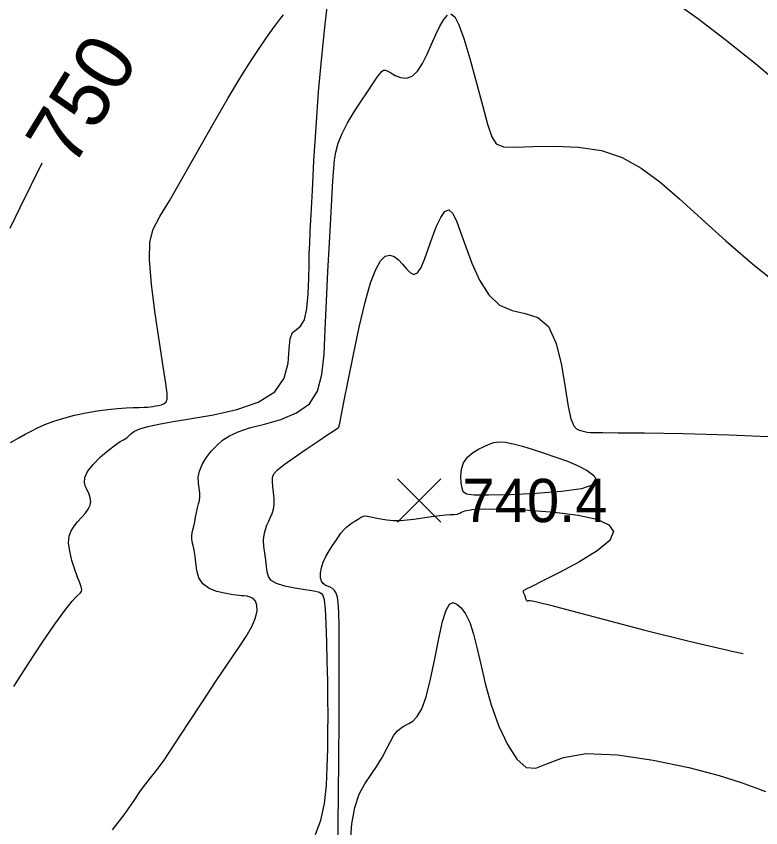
# Model space of a CAD drawing. Extents: x 2566142 to 2571431, y 418755 to 421584.
# Drawn here: x 2567510.6 to 2567768.3, y 420429 to 420710 of the extents above; entities that cross this region are included whole.
import ezdxf

# ---------------------------------------------------------------- set-up
doc = ezdxf.new("R2010")
doc.units = 0
for name, color, linetype in [('Contour_ADS_Label_Major', 7, 'Continuous'), ('Contour_ADS_Major', 7, 'Continuous'), ('Contour_ADS_Minor', 7, 'Continuous'), ('Contour_ADS_Spot_Elevation', 7, 'Continuous')]:
    doc.layers.add(name, color=color, linetype=linetype)

# ---------------------------------------------------------------- blocks, each defined once
blk = doc.blocks.new('S750')
at = {"layer": 'Contour_ADS_Spot_Elevation'}
for p, q in [((-0.5, 0.498), (0.5, -0.498)), ((-0.498, -0.5), (0.498, 0.5))]:
    blk.add_line(p, q, dxfattribs=at)

msp = doc.modelspace()

# ---------------------------------------------------------------- linework, layer by layer
at = {"layer": 'Contour_ADS_Major'}
for points in [[(2567508.51, 420636.59), (2567511.88, 420643.75), (2567515.73, 420651.47), (2567519.59, 420659.15)], [(2567621.88, 420422.89), (2567622.06, 420430.49), (2567622.18, 420440.5), (2567622.27, 420452.9), (2567622.33, 420466.44), (2567622.37, 420479.56), (2567622.38, 420490.67), (2567622.35, 420498.61), (2567622.25, 420503.76), (2567622.06, 420506.91), (2567621.75, 420508.83), (2567621.3, 420510.17), (2567620.71, 420511.15), (2567620.01, 420511.82), (2567619.21, 420512.29), (2567618.35, 420512.63), (2567617.51, 420512.98), (2567616.77, 420513.5), (2567616.21, 420514.32), (2567615.92, 420515.56), (2567615.91, 420517.15), (2567616.21, 420518.98), (2567616.83, 420520.93), (2567617.75, 420522.92), (2567618.87, 420524.86), (2567620.06, 420526.68), (2567621.17, 420528.32), (2567622.12, 420529.73), (2567622.99, 420530.95), (2567623.88, 420532.04), (2567624.92, 420533.08), (2567626.19, 420534.1), (2567627.56, 420535.06), (2567628.88, 420535.88), (2567629.99, 420536.49), (2567630.8, 420536.83), (2567631.46, 420536.94), (2567632.21, 420536.85), (2567633.27, 420536.61), (2567634.8, 420536.27), (2567636.73, 420535.9), (2567638.91, 420535.59), (2567641.22, 420535.4), (2567643.54, 420535.41), (2567645.85, 420535.58), (2567648.16, 420535.86), (2567650.49, 420536.19), (2567652.82, 420536.53), (2567655.09, 420536.84), (2567657.23, 420537.11), (2567659.17, 420537.3), (2567660.83, 420537.4), (2567662.22, 420537.48), (2567663.31, 420537.61), (2567664.12, 420537.85), (2567664.75, 420538.25), (2567665.86, 420538.72), (2567668.23, 420539.14), (2567672.62, 420539.37), (2567679.48, 420539.32), (2567687.96, 420538.94), (2567696.89, 420538.24), (2567705.11, 420537.19), (2567711.56, 420535.77), (2567715.76, 420533.9), (2567717.36, 420531.5), (2567716.01, 420528.48), (2567711.64, 420524.86), (2567705.38, 420520.99), (2567698.64, 420517.36), (2567692.85, 420514.44), (2567689.09, 420512.56), (2567687.1, 420511.56), (2567686.31, 420511.14), (2567686.13, 420511.01), (2567686.06, 420510.91), (2567686.03, 420510.8), (2567686.04, 420510.67), (2567686.08, 420510.51), (2567686.17, 420510.32), (2567686.29, 420510.1), (2567686.42, 420509.86), (2567686.54, 420509.6), (2567686.63, 420509.33), (2567686.71, 420509.05), (2567686.78, 420508.76), (2567686.87, 420508.46), (2567686.98, 420508.15), (2567687.11, 420507.87), (2567687.25, 420507.65), (2567687.39, 420507.52), (2567687.53, 420507.52), (2567687.73, 420507.58)], [(2567687.73, 420507.58), (2567688.02, 420507.66), (2567688.46, 420507.69), (2567689.28, 420507.59), (2567691.3, 420507.12), (2567695.52, 420506.03), (2567702.95, 420504.07), (2567714.18, 420501.08), (2567728.18, 420497.44), (2567743.54, 420493.6), (2567758.82, 420490.06), (2567762.22, 420489.37)]]:
    msp.add_lwpolyline(points, dxfattribs=at)
msp.add_lwpolyline([(2567693.36, 420558.64), (2567697.41, 420557.28), (2567701.39, 420555.85), (2567705.08, 420554.32), (2567708.23, 420552.7), (2567710.54, 420550.99), (2567711.42, 420549.28), (2567710.22, 420547.69), (2567706.27, 420546.35), (2567699.31, 420545.35), (2567690.55, 420544.68), (2567681.61, 420544.27), (2567674.07, 420544.1), (2567669.15, 420544.14), (2567666.49, 420544.48), (2567665.33, 420545.24), (2567664.9, 420546.54), (2567664.62, 420548.43), (2567664.49, 420550.71), (2567664.71, 420553.11), (2567665.43, 420555.36), (2567666.78, 420557.25), (2567668.57, 420558.78), (2567670.57, 420560.02), (2567672.51, 420561.01), (2567674.25, 420561.81), (2567675.91, 420562.37), (2567677.73, 420562.62), (2567679.92, 420562.49), (2567682.65, 420561.95), (2567685.87, 420561.07), (2567689.47, 420559.93), (2567693.36, 420558.64)], close=True, dxfattribs=at)
at = {"layer": 'Contour_ADS_Minor'}
for points in [[(2567613.07, 420649.62), (2567613.64, 420659.95), (2567614.37, 420671.57), (2567615.26, 420683.79), (2567616.32, 420695.88), (2567617.48, 420707.2), (2567618.66, 420717.1)], [(2567738.57, 420714.87), (2567746.36, 420709.34), (2567755.89, 420702.06), (2567766.44, 420693.57), (2567777.28, 420684.42)], [(2567508.56, 420562.4), (2567511.44, 420563.94), (2567513.69, 420565.22), (2567515.71, 420566.35), (2567517.88, 420567.45), (2567520.52, 420568.6), (2567523.6, 420569.75), (2567527.05, 420570.85), (2567530.77, 420571.83), (2567534.65, 420572.65), (2567538.53, 420573.29), (2567542.26, 420573.78), (2567545.66, 420574.12), (2567548.59, 420574.33), (2567551.06, 420574.45), (2567553.08, 420574.52), (2567554.7, 420574.57), (2567555.96, 420574.64), (2567556.98, 420574.74), (2567557.88, 420574.86), (2567558.8, 420575.01), (2567559.82, 420575.19), (2567560.87, 420575.45), (2567561.81, 420575.85), (2567562.52, 420576.45), (2567562.87, 420577.4), (2567562.83, 420579.29), (2567562.37, 420582.81), (2567561.45, 420588.63), (2567560.12, 420597.08), (2567558.65, 420607.05), (2567557.4, 420617.04), (2567556.7, 420625.59), (2567556.86, 420631.69), (2567558.01, 420636.23), (2567560.22, 420640.58), (2567563.57, 420646.1), (2567568.03, 420653.76), (2567573.22, 420662.91), (2567578.65, 420672.49), (2567583.82, 420681.45), (2567588.33, 420688.96), (2567592.14, 420695), (2567595.32, 420699.79), (2567597.91, 420703.53), (2567599.99, 420706.43), (2567601.68, 420708.66), (2567603.13, 420710.42)], [(2567661.07, 420710.75), (2567662.37, 420709.76), (2567663.83, 420707.03), (2567665.56, 420702.23), (2567667.61, 420695.3), (2567669.81, 420687.21), (2567671.93, 420679.21), (2567673.74, 420672.55), (2567675.16, 420668.15), (2567676.76, 420665.75), (2567679.24, 420664.78), (2567683.31, 420664.68), (2567689.42, 420664.89), (2567696.99, 420665.01), (2567705.18, 420664.65), (2567713.16, 420663.42), (2567720.3, 420661.02), (2567726.87, 420657.41), (2567733.34, 420652.64), (2567740.19, 420646.74), (2567747.82, 420639.82), (2567756.25, 420632.2), (2567765.44, 420624.24), (2567775.32, 420616.31)], [(2567575.13, 420513.38), (2567573.76, 420515.53), (2567573.04, 420518.04), (2567572.71, 420520.65), (2567572.5, 420523.06), (2567572.2, 420525.06), (2567571.84, 420526.67), (2567571.52, 420527.98), (2567571.32, 420529.1), (2567571.31, 420530.09), (2567571.47, 420531.08), (2567571.73, 420532.14), (2567572.04, 420533.39), (2567572.36, 420534.88), (2567572.67, 420536.52), (2567572.99, 420538.18), (2567573.32, 420539.74), (2567573.66, 420541.1), (2567573.95, 420542.34), (2567574.12, 420543.59), (2567574.1, 420544.96), (2567573.89, 420546.54), (2567573.65, 420548.34), (2567573.6, 420550.33), (2567573.96, 420552.49), (2567574.9, 420554.77), (2567576.33, 420557.09), (2567578.07, 420559.32), (2567579.99, 420561.38), (2567581.99, 420563.16), (2567584.34, 420564.72), (2567587.35, 420566.12), (2567591.36, 420567.43), (2567596.5, 420568.75), (2567602.18, 420570.37), (2567607.62, 420572.61), (2567612.05, 420575.8), (2567614.88, 420580.2), (2567616.41, 420585.91), (2567617.11, 420592.99), (2567617.49, 420601.49), (2567617.93, 420611.28), (2567618.45, 420621.58), (2567618.99, 420631.45), (2567619.46, 420639.94), (2567619.81, 420646.35), (2567620.07, 420651.01), (2567620.28, 420654.48), (2567620.49, 420657.35), (2567620.76, 420660.11), (2567621.22, 420662.95), (2567622.04, 420665.99), (2567623.37, 420669.32), (2567625.29, 420673), (2567627.59, 420676.82), (2567629.98, 420680.51), (2567632.16, 420683.79), (2567633.92, 420686.45), (2567635.27, 420688.48), (2567636.29, 420689.93), (2567637.08, 420690.85), (2567637.72, 420691.3), (2567638.36, 420691.32), (2567639.15, 420690.98), (2567640.27, 420690.33), (2567641.79, 420689.49), (2567643.64, 420688.76), (2567645.64, 420688.54), (2567647.63, 420689.19), (2567649.5, 420690.97), (2567651.23, 420693.65), (2567652.84, 420696.88), (2567654.36, 420700.31), (2567655.82, 420703.62), (2567657.21, 420706.54), (2567658.54, 420708.87), (2567659.82, 420710.35)], [(2567509.71, 420477.88), (2567514.85, 420485.87), (2567519.68, 420493.18), (2567523.95, 420499.42), (2567527.44, 420504.24), (2567529.97, 420507.4), (2567531.64, 420509.23), (2567532.64, 420510.21), (2567533.12, 420510.82), (2567533.24, 420511.48), (2567533.05, 420512.41), (2567532.56, 420513.78), (2567531.81, 420515.76), (2567530.84, 420518.43), (2567529.86, 420521.53), (2567529.06, 420524.7), (2567528.68, 420527.59), (2567528.86, 420529.94), (2567529.54, 420531.83), (2567530.57, 420533.42), (2567531.81, 420534.89), (2567533.13, 420536.35), (2567534.38, 420537.81), (2567535.42, 420539.25), (2567536.11, 420540.63), (2567536.35, 420541.94), (2567536.2, 420543.2), (2567535.78, 420544.44), (2567535.19, 420545.72), (2567534.57, 420547.06), (2567534.17, 420548.56), (2567534.3, 420550.3), (2567535.26, 420552.38), (2567537.2, 420554.81), (2567539.78, 420557.35), (2567542.51, 420559.71), (2567544.89, 420561.56), (2567546.57, 420562.71), (2567547.65, 420563.32), (2567548.33, 420563.68), (2567548.84, 420564.03), (2567549.39, 420564.61), (2567550.19, 420565.37), (2567551.45, 420566.24), (2567553.36, 420567.1), (2567556.12, 420567.92), (2567559.9, 420568.73), (2567564.87, 420569.61), (2567571.19, 420570.66), (2567578.82, 420571.97), (2567586.88, 420573.79), (2567594.31, 420576.36), (2567600.03, 420579.95), (2567603.3, 420584.64), (2567604.68, 420589.8), (2567605.06, 420594.63), (2567605.34, 420598.33), (2567606.22, 420600.4), (2567607.55, 420601.52), (2567609.03, 420602.68), (2567610.32, 420604.87), (2567611.17, 420608.76), (2567611.64, 420613.81), (2567611.86, 420619.19), (2567611.95, 420624.05), (2567612.03, 420627.85), (2567612.16, 420631.31), (2567612.35, 420635.46), (2567612.65, 420641.32), (2567613.07, 420649.62)], [(2567596.94, 420521.67), (2567596.59, 420524.02), (2567596.3, 420526.38), (2567596.21, 420528.6), (2567596.39, 420530.55), (2567596.8, 420532.26), (2567597.36, 420533.78), (2567597.99, 420535.17), (2567598.62, 420536.47), (2567599.18, 420537.8), (2567599.6, 420539.26), (2567599.82, 420540.96), (2567599.8, 420542.94), (2567599.63, 420545.06), (2567599.4, 420547.11), (2567599.23, 420548.89), (2567599.26, 420550.28), (2567599.76, 420551.51), (2567601.01, 420552.88), (2567603.31, 420554.73), (2567606.79, 420557.22), (2567610.93, 420560.07), (2567615.05, 420562.84), (2567618.44, 420565.11), (2567620.62, 420566.56), (2567621.74, 420567.3), (2567622.16, 420567.59), (2567622.23, 420567.64), (2567622.24, 420567.65), (2567622.25, 420567.66), (2567622.26, 420567.67), (2567622.27, 420567.68), (2567622.28, 420567.69), (2567622.29, 420567.71), (2567622.3, 420567.75), (2567622.32, 420567.81), (2567622.37, 420568.03), (2567622.57, 420569.02), (2567623.07, 420571.52), (2567624, 420576.29), (2567625.45, 420583.71), (2567627.29, 420592.84), (2567629.32, 420602.35), (2567631.36, 420610.96), (2567633.26, 420617.6), (2567635.02, 420622.3), (2567636.68, 420625.3), (2567638.28, 420626.87), (2567639.86, 420627.28), (2567641.41, 420626.78), (2567642.91, 420625.64), (2567644.34, 420624.11), (2567645.7, 420622.49), (2567647, 420621.16), (2567648.26, 420620.54), (2567649.51, 420621.06), (2567650.75, 420622.99), (2567652.02, 420626.02), (2567653.32, 420629.71), (2567654.68, 420633.61), (2567656.09, 420637.29), (2567657.54, 420640.33), (2567658.96, 420642.35), (2567660.33, 420642.95), (2567661.62, 420641.83), (2567662.93, 420639.15), (2567664.41, 420635.17), (2567666.16, 420630.15), (2567668.32, 420624.41), (2567670.95, 420618.63), (2567674.12, 420613.54), (2567677.89, 420609.88), (2567682.24, 420608.06), (2567686.8, 420607.09), (2567691.14, 420605.67), (2567694.8, 420602.48), (2567697.47, 420596.67), (2567699.3, 420589.18), (2567700.58, 420581.45), (2567701.6, 420574.89), (2567702.58, 420570.56), (2567703.57, 420568.18), (2567704.55, 420567.1), (2567705.49, 420566.68), (2567706.39, 420566.38), (2567707.3, 420566.13), (2567708.27, 420565.93), (2567709.36, 420565.81), (2567710.8, 420565.78), (2567713.61, 420565.78), (2567718.96, 420565.77), (2567728.05, 420565.67), (2567741.46, 420565.44), (2567757.41, 420565.01), (2567773.48, 420564.35)], [(2567614.17, 420426.6), (2567616.03, 420431.57), (2567617.23, 420437.33), (2567617.92, 420443.6), (2567618.26, 420450.04), (2567618.39, 420456.31), (2567618.47, 420462.16), (2567618.5, 420467.82), (2567618.47, 420473.59), (2567618.39, 420479.78), (2567618.24, 420486.56), (2567618.04, 420493.41), (2567617.81, 420499.65), (2567617.57, 420504.63), (2567617.28, 420507.85), (2567616.71, 420509.63), (2567615.57, 420510.48), (2567613.57, 420510.91), (2567610.57, 420511.35), (2567607.02, 420511.91), (2567603.5, 420512.62), (2567600.61, 420513.51), (2567598.8, 420514.62), (2567597.86, 420515.97), (2567597.46, 420517.58), (2567597.24, 420519.49), (2567596.94, 420521.67)], [(2567543.84, 420428.28), (2567547.9, 420433.47), (2567551.14, 420438.1), (2567553.62, 420441.76), (2567555.47, 420444.24), (2567557.1, 420446.24), (2567559.02, 420448.66), (2567561.72, 420452.4), (2567565.52, 420458.07), (2567570.11, 420465.1), (2567575.02, 420472.63), (2567579.75, 420479.8), (2567583.9, 420485.93), (2567587.36, 420491), (2567590.11, 420495.2), (2567592.11, 420498.7), (2567593.36, 420501.65), (2567593.92, 420504.09), (2567593.91, 420506.01), (2567593.42, 420507.42), (2567592.58, 420508.34), (2567591.52, 420508.87), (2567590.41, 420509.13), (2567589.4, 420509.25), (2567588.58, 420509.33), (2567587.76, 420509.41), (2567586.67, 420509.55), (2567585.02, 420509.78), (2567582.69, 420510.16), (2567579.97, 420510.79), (2567577.31, 420511.83), (2567575.13, 420513.38)], [(2567635.45, 420450.3), (2567637.22, 420453.3), (2567638.74, 420456.24), (2567640.09, 420458.9), (2567641.34, 420461.07), (2567642.57, 420462.59), (2567643.81, 420463.62), (2567645.09, 420464.37), (2567646.44, 420465.05), (2567647.89, 420465.94), (2567649.4, 420467.46), (2567650.95, 420470.1), (2567652.49, 420474.34), (2567654, 420480.41), (2567655.46, 420487.49), (2567656.86, 420494.51), (2567658.17, 420500.39), (2567659.41, 420504.29), (2567660.61, 420506.36), (2567661.84, 420506.95), (2567663.15, 420506.45), (2567664.58, 420505.14), (2567666.07, 420503.02), (2567667.54, 420500), (2567668.92, 420495.99), (2567670.17, 420490.95), (2567671.47, 420485.04), (2567673, 420478.49), (2567674.99, 420471.49), (2567677.56, 420464.37), (2567680.58, 420457.84), (2567683.84, 420452.73), (2567687.14, 420449.84), (2567690.45, 420449.66), (2567694.44, 420451.25), (2567699.97, 420453.34), (2567707.92, 420454.66), (2567718.7, 420454.24), (2567731.07, 420452.41), (2567743.38, 420449.8), (2567753.94, 420447.03), (2567761.51, 420444.65), (2567766.57, 420442.81), (2567769.98, 420441.59)], [(2567626.23, 420424.21), (2567626.76, 420430.38), (2567627.76, 420436.01), (2567629.33, 420440.57), (2567631.3, 420444.24), (2567633.41, 420447.37), (2567635.45, 420450.3)]]:
    msp.add_lwpolyline(points, dxfattribs=at)

# ---------------------------------------------------------------- block references
at = {"layer": 'Contour_ADS_Spot_Elevation', "xscale": 15, "yscale": 15}
msp.add_blockref('S750', (2567650.06, 420542.29), dxfattribs=at)

# ---------------------------------------------------------------- texts
at = {"layer": 'Contour_ADS_Label_Major'}
msp.add_text('750', height=20, rotation=58.5328, dxfattribs=at).set_placement((2567530.01, 420657))
at = {"layer": 'Contour_ADS_Spot_Elevation'}
msp.add_text('740.4', height=15, dxfattribs=at).set_placement((2567665.06, 420534.79))

doc.saveas('drawing.dxf')
